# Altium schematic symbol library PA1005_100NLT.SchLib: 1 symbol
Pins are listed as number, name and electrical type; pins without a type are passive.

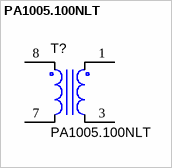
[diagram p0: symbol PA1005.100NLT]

## PA1005.100NLT
designator T?
XFRMR CURR SENSE 2.0MH 1:100 SMD; Manufacturer: Pulse Engineering; CompType: Transformer; Rp: .000750; U/M: EA
footprint PA1005.XXXNL (PULSE ENGINEERING PA1005.XXXNL SERIES)
pins: 1, 3, 7, 8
